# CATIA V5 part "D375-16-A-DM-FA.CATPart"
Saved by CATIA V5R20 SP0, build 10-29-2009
Part number: D375-16-A-DM-FA
Bounding box of the stored display mesh (mm): x -14 to 0, y -8 to 8, z -8 to 8
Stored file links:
  C:\Users\Utente\Desktop\IO LAVORO\3D X SITO CF\X SITO\PLASTICA\D375\D375-16-A-DM-FA.CATPart
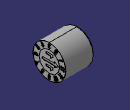
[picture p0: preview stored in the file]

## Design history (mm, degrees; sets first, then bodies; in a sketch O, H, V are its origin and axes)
Set1
  DatumSurface1 to DatumSurface216 "D375-16-A-DM-FA"
Body1 (main body)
